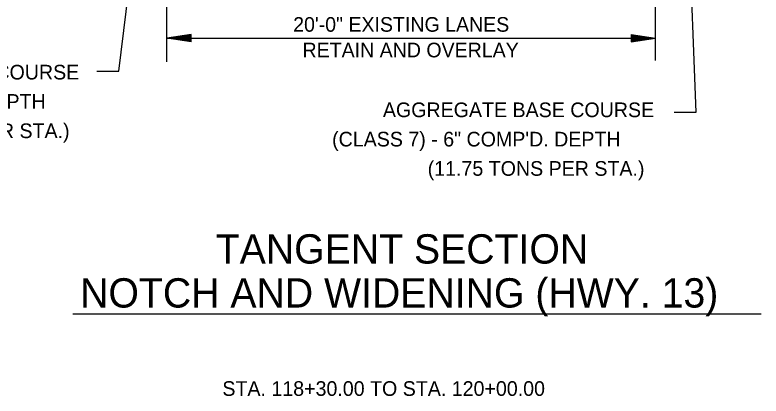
# Model space of a CAD drawing. Extents: x 2478 to 3210, y 439 to 841.
# Drawn here: x 2996 to 3057, y 556.3 to 587.5 of the extents above; entities that cross this region are included whole.
import ezdxf

# ---------------------------------------------------------------- set-up
doc = ezdxf.new("R2010")
doc.units = 0
doc.layers.add('R_Annotation', color=7, linetype='Continuous')
doc.layers.add('R_Dimension', color=7, linetype='Continuous')

msp = doc.modelspace()

# ---------------------------------------------------------------- linework, layer by layer
at = {"layer": 'R_Annotation'}
msp.add_line((3000.679, 562.975), (3057.028, 562.975), dxfattribs=at)
at = {"layer": 'R_Dimension'}
for p, q in [((3008.387, 583.607), (3008.387, 594.169)), ((3048.387, 583.71), (3048.387, 594.11)), ((3010.387, 585.858), (3008.387, 585.558)), ((3010.387, 585.808), (3008.721, 585.558)), ((3010.387, 585.757), (3009.065, 585.558)), ((3010.387, 585.258), (3010.387, 585.858)), ((3046.387, 585.858), (3048.387, 585.558)), ((3046.387, 585.858), (3046.387, 585.258)), ((3046.387, 585.808), (3048.053, 585.558)), ((3046.387, 585.757), (3047.709, 585.558)), ((3008.387, 585.558), (3048.387, 585.558)), ((3010.387, 585.258), (3008.387, 585.558)), ((3010.387, 585.308), (3008.721, 585.558)), ((3010.387, 585.359), (3009.065, 585.558)), ((3010.387, 585.707), (3009.398, 585.558)), ((3010.387, 585.409), (3009.398, 585.558)), ((3010.387, 585.656), (3009.737, 585.558)), ((3010.387, 585.461), (3009.737, 585.558)), ((3010.387, 585.605), (3010.071, 585.558)), ((3010.387, 585.511), (3010.071, 585.558)), ((3046.387, 585.707), (3047.376, 585.558)), ((3046.387, 585.655), (3047.037, 585.558)), ((3046.387, 585.605), (3046.703, 585.558)), ((3046.387, 585.258), (3048.387, 585.558)), ((3046.387, 585.46), (3047.037, 585.558)), ((3046.387, 585.359), (3047.709, 585.558)), ((3046.387, 585.308), (3048.053, 585.558)), ((3046.387, 585.409), (3047.376, 585.558)), ((3046.387, 585.511), (3046.703, 585.558))]:
    msp.add_line(p, q, dxfattribs=at)
for points in [[(3002.668, 582.834), (3004.466, 582.834), (3005.863, 594.421)], [(3049.91, 579.489), (3051.708, 579.489), (3051.128, 594.374)]]:
    msp.add_lwpolyline(points, dxfattribs=at)

# ---------------------------------------------------------------- texts
at = {"layer": 'R_Annotation'}
for s, height, p in [('20\'-0" EXISTING LANES', 1.197, (3018.728, 586.075)), ('RETAIN AND OVERLAY', 1.197, (3019.492, 583.98)), ('AGGREGATE BASE COURSE', 1.2, (2979.015, 582.166)), ('(CLASS 7) - 6" COMP\'D. DEPTH', 1.2, (2974.858, 579.766)), ('AGGREGATE BASE COURSE', 1.2, (3026.072, 579.083)), ('(11.75 TONS PER STA.)', 1.2, (2982.681, 577.366)), ('(CLASS 7) - 6" COMP\'D. DEPTH', 1.2, (3021.914, 576.683)), ('(11.75 TONS PER STA.)', 1.2, (3029.738, 574.283)), ('TANGENT SECTION', 2.4, (3012.39, 567.097)), ('NOTCH AND WIDENING (HWY. 13)', 2.4, (3001.287, 563.497)), ('STA. 118+30.00 TO STA. 120+00.00', 1.2, (3012.933, 556.268))]:
    msp.add_text(s, height=height, dxfattribs=at).set_placement(p)

doc.saveas('drawing.dxf')
